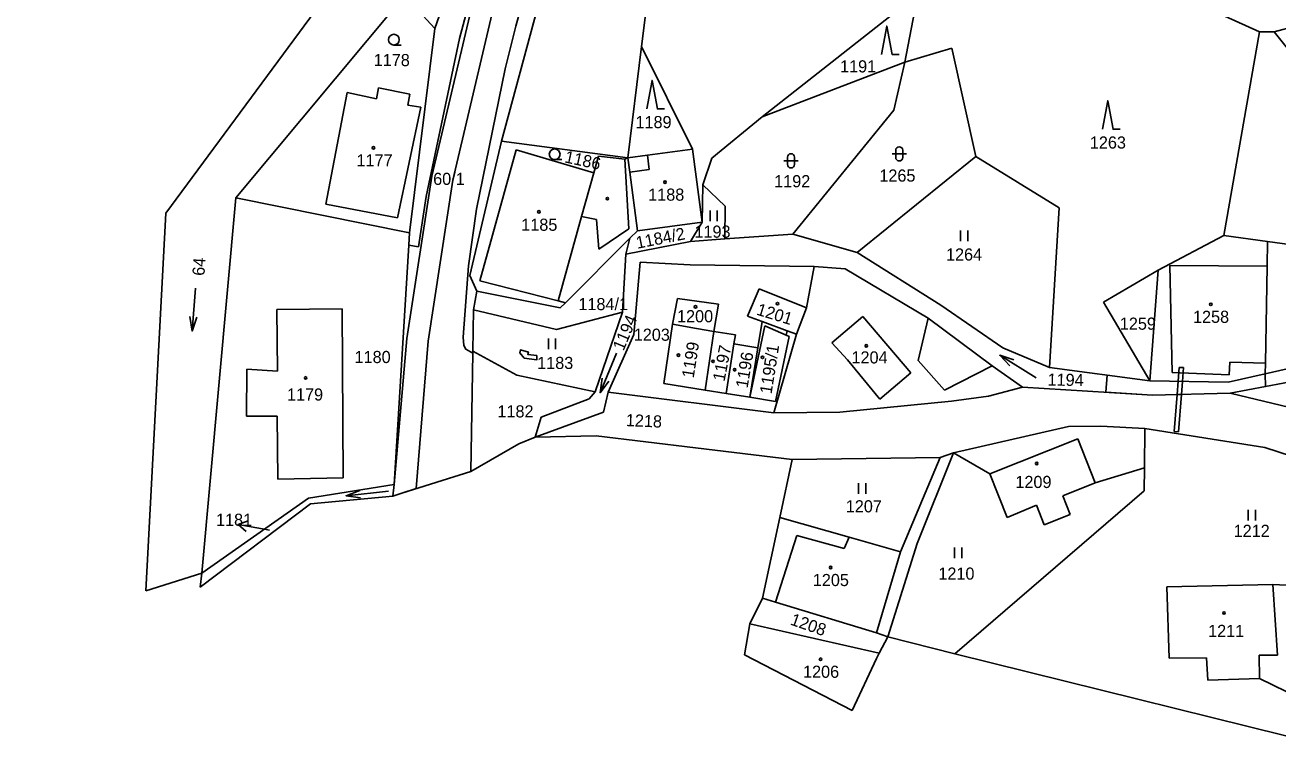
# Model space of a CAD drawing. Extents: x -670359 to -660124, y -978807 to -970072.
# Drawn here: x -670226.4 to -670050.9, y -978154.2 to -978052.1 of the extents above; entities that cross this region are included whole.
import ezdxf

# ---------------------------------------------------------------- set-up
doc = ezdxf.new("R2010")
doc.units = 0
for name, color, linetype in [('Hranice kat_území', 7, 'Continuous'), ('Hranice parcel', 7, 'Continuous'), ('Parcelní čísla', 7, 'Continuous'), ('Vnitřní kresba', 7, 'Continuous'), ('Věcná břemena k části', 7, 'Continuous'), ('Značky budov', 7, 'Continuous'), ('Značky kultur', 7, 'Continuous')]:
    doc.layers.add(name, color=color, linetype=linetype)

msp = doc.modelspace()

# ---------------------------------------------------------------- linework, layer by layer
at = {"layer": 'Hranice kat_území'}
for points in [[(-670206.64, -978078.45), (-670182.02, -978044.99)], [(-670209.48, -978131.38), (-670206.64, -978078.45)], [(-670157.22, -978110.78), (-670154.93, -978109.83)], [(-670154.93, -978109.83), (-670146.36, -978109.64)], [(-670146.36, -978109.64), (-670132.46, -978111.32)], [(-670163.94, -978114.63), (-670157.22, -978110.78)], [(-670132.46, -978111.32), (-670118.94, -978112.96)], [(-670120.66, -978121.07), (-670118.94, -978112.96)], [(-670173.62, -978117.69), (-670163.94, -978114.63)], [(-670186.41, -978119.18), (-670174.87, -978118.08)], [(-670174.87, -978118.08), (-670173.62, -978117.69)], [(-670201.87, -978130.85), (-670186.41, -978119.18)], [(-670123.06, -978132.41), (-670120.66, -978121.07)], [(-670209.48, -978131.38), (-670201.62, -978128.9)], [(-670201.62, -978128.9), (-670201.87, -978130.85)], [(-670124.85, -978136.01), (-670123.06, -978132.41)], [(-670125.58, -978140.33), (-670124.85, -978136.01)], [(-670106.72, -978140.12), (-670105.53, -978137.83)], [(-670105.53, -978137.83), (-670096.14, -978140.17)], [(-670125.58, -978140.33), (-670110.53, -978148.14)], [(-670110.53, -978148.14), (-670107.1, -978140.86)], [(-670107.1, -978140.86), (-670106.72, -978140.12)], [(-670096.14, -978140.17), (-670039.59, -978154.22)]]:
    msp.add_lwpolyline(points, dxfattribs=at)
at = {"layer": 'Hranice parcel'}
for p, q in [((-670123.73, -978097.32), (-670123.14, -978093.61)), ((-670123.14, -978093.61), (-670119.64, -978094.92)), ((-670119.64, -978094.92), (-670119.75, -978095.56)), ((-670124.83, -978104.24), (-670123.73, -978097.32)), ((-670121.25, -978104.82), (-670124.83, -978104.24)), ((-670091.23, -978114.98), (-670096.34, -978112.05)), ((-670088.81, -978121.11), (-670091.23, -978114.98)), ((-670076.46, -978116.25), (-670069.58, -978114.15)), ((-670076.46, -978116.25), (-670080.99, -978118.05)), ((-670080.99, -978118.05), (-670079.96, -978120.65)), ((-670084.69, -978119.35), (-670088.81, -978121.11)), ((-670083.6, -978122.1), (-670084.69, -978119.35)), ((-670079.96, -978120.65), (-670083.6, -978122.1))]:
    msp.add_line(p, q, dxfattribs=at)
for points in [[(-670172.63, -978082.94), (-670171.28, -978083.15), (-670170.18, -978076.11), (-670165.52, -978053.97), (-670162.38, -978042.27), (-670156.72, -978020.75), (-670154.86, -978010.1), (-670154.63, -978006.17), (-670154.76, -977993.05), (-670158.01, -977978.52), (-670176.81, -977929.42)], [(-670163.67, -978098.07), (-670164.62, -978097.52), (-670164.93, -978097), (-670165.03, -978095.83), (-670164.26, -978085.83), (-670163.16, -978077.87), (-670159.11, -978058.23), (-670157.62, -978052.26), (-670152.59, -978034.05), (-670149.21, -978019.82), (-670148.28, -978014.22), (-670147.57, -978006.49), (-670147.34, -977998.17), (-670147.68, -977989.98), (-670148.49, -977985.18)], [(-670148.99, -978028.93), (-670159.63, -978068.36)], [(-670136.86, -978029.74), (-670140.01, -978055.12)], [(-670164.52, -978039.85), (-670168.99, -978052.57)], [(-670083.53, -978039.41), (-670053.47, -978053.05)], [(-670196.85, -978076.29), (-670173.76, -978048.61)], [(-670123.1, -978064.97), (-670101.33, -978047.75)], [(-670101.33, -978047.75), (-670103.12, -978057.29)], [(-670168.99, -978052.57), (-670171.72, -978049.59)], [(-670048.28, -978052.22), (-670051.39, -978053.04)], [(-670168.99, -978052.57), (-670172.53, -978081.22)], [(-670053.47, -978053.05), (-670058.45, -978081.6)], [(-670051.39, -978053.04), (-670053.47, -978053.05)], [(-670140.01, -978055.12), (-670141.94, -978070.7)], [(-670132.87, -978069.5), (-670140.01, -978055.12)], [(-670103.12, -978057.29), (-670096.54, -978055.34)], [(-670096.54, -978055.34), (-670093.21, -978070.49)], [(-670123.1, -978064.97), (-670103.12, -978057.29)], [(-670103.12, -978057.29), (-670104.69, -978064)], [(-670177.17, -978062.41), (-670176.85, -978060.87)], [(-670176.85, -978060.87), (-670172.46, -978061.78)], [(-670184.26, -978077.21), (-670181.26, -978061.55)], [(-670181.26, -978061.55), (-670177.17, -978062.41)], [(-670172.46, -978061.78), (-670172.78, -978063.33)], [(-670170.95, -978063.58), (-670174.2, -978079.09)], [(-670172.78, -978063.33), (-670170.95, -978063.58)], [(-670104.69, -978064), (-670118.83, -978081.4)], [(-670130.19, -978070.75), (-670123.1, -978064.97)], [(-670159.63, -978068.36), (-670164.09, -978087.2)], [(-670162.66, -978087.94), (-670157.59, -978069.58)], [(-670141.94, -978070.7), (-670159.63, -978068.36)], [(-670157.59, -978069.58), (-670146.69, -978072.78)], [(-670132.87, -978069.5), (-670139.2, -978070.34)], [(-670131.53, -978079.72), (-670132.87, -978069.5)], [(-670146.69, -978072.78), (-670146.04, -978070.47)], [(-670146.04, -978070.47), (-670142.36, -978070.9)], [(-670142.36, -978070.9), (-670141.94, -978070.7)], [(-670139.2, -978070.34), (-670141.94, -978070.7)], [(-670141.94, -978070.7), (-670141.68, -978072.7)], [(-670131.42, -978074.5), (-670130.19, -978070.75)], [(-670093.21, -978070.49), (-670109.81, -978083.95)], [(-670093.21, -978070.49), (-670081.51, -978077.7)], [(-670141.68, -978072.7), (-670140.6, -978080.91)], [(-670131.53, -978079.72), (-670131.42, -978074.5)], [(-670131.42, -978074.5), (-670128.32, -978077.49)], [(-670201.62, -978128.9), (-670196.85, -978076.29)], [(-670172.53, -978081.22), (-670196.85, -978076.29)], [(-670174.2, -978079.09), (-670184.26, -978077.21)], [(-670128.32, -978077.49), (-670128.36, -978082.05)], [(-670081.51, -978077.7), (-670082.88, -978100.08)], [(-670140.6, -978080.91), (-670131.53, -978079.72)], [(-670131.53, -978079.72), (-670133.16, -978082.41)], [(-670172.53, -978081.22), (-670172.63, -978082.94)], [(-670150.69, -978090.99), (-670141.65, -978081.96)], [(-670141.65, -978081.96), (-670142.22, -978084.18)], [(-670140.6, -978080.91), (-670141.65, -978081.96)], [(-670128.36, -978082.05), (-670133.16, -978082.41)], [(-670118.83, -978081.4), (-670128.36, -978082.05)], [(-670109.81, -978083.95), (-670118.83, -978081.4)], [(-670058.45, -978081.6), (-670067.65, -978086.44)], [(-670058.45, -978081.6), (-670052.31, -978082.43)], [(-670172.63, -978082.94), (-670174.67, -978116.45)], [(-670133.16, -978082.41), (-670142.22, -978084.18)], [(-670052.31, -978082.43), (-670052.38, -978085.89)], [(-670052.31, -978082.43), (-670030.83, -978085.37)], [(-670142.22, -978084.18), (-670142.69, -978092.33)], [(-670141.11, -978095.46), (-670140.23, -978085.31)], [(-670140.23, -978085.31), (-670133.19, -978085.69)], [(-670098.1, -978091.32), (-670109.81, -978083.95)], [(-670164.09, -978087.2), (-670163.07, -978089.37)], [(-670133.19, -978085.69), (-670115.82, -978085.9)], [(-670115.82, -978085.9), (-670116.91, -978091.73)], [(-670111.51, -978086.26), (-670115.82, -978085.9)], [(-670099.87, -978093.15), (-670111.51, -978086.26)], [(-670067.65, -978086.44), (-670075.29, -978090.94)], [(-670067.65, -978086.44), (-670068.81, -978101.95)], [(-670052.38, -978085.89), (-670052.63, -978099.48)], [(-670151.68, -978090.74), (-670162.66, -978087.94)], [(-670123.53, -978089.04), (-670125.16, -978092.87)], [(-670116.91, -978091.73), (-670123.53, -978089.04)], [(-670163.07, -978089.37), (-670163.57, -978092.01)], [(-670151.4, -978091.7), (-670163.07, -978089.37)], [(-670150.69, -978090.99), (-670151.68, -978090.74)], [(-670134.99, -978090.39), (-670135.66, -978093.99)], [(-670129.26, -978091.21), (-670134.99, -978090.39)], [(-670191.1, -978091.95), (-670181.94, -978091.86)], [(-670191.01, -978100.59), (-670191.1, -978091.95)], [(-670181.94, -978091.86), (-670181.84, -978115.54)], [(-670163.57, -978092.01), (-670163.66, -978097.77)], [(-670151.91, -978094.74), (-670163.57, -978092.01)], [(-670142.69, -978092.33), (-670151.91, -978094.74)], [(-670150.69, -978090.99), (-670151.4, -978091.7)], [(-670142.69, -978092.33), (-670146.53, -978103.5)], [(-670129.87, -978095.01), (-670129.26, -978091.21)], [(-670116.91, -978091.73), (-670118.3, -978095.4)], [(-670089.42, -978097.31), (-670098.1, -978091.32)], [(-670075.29, -978090.94), (-670068.81, -978101.95)], [(-670135.66, -978093.99), (-670136.92, -978102.3)], [(-670132.32, -978094.62), (-670135.66, -978093.99)], [(-670125.16, -978092.87), (-670123.14, -978093.61)], [(-670090.88, -978099.86), (-670099.87, -978093.15)], [(-670144.69, -978103.51), (-670141.11, -978095.46)], [(-670129.87, -978095.01), (-670132.32, -978094.62)], [(-670131.12, -978103.23), (-670129.87, -978095.01)], [(-670126.88, -978095.5), (-670129.87, -978095.01)], [(-670127.09, -978096.78), (-670126.88, -978095.5)], [(-670118.3, -978095.4), (-670121.47, -978106.42)], [(-670119.32, -978095.75), (-670121.25, -978104.82)], [(-670119.75, -978095.56), (-670119.32, -978095.75)], [(-670119.64, -978094.92), (-670118.3, -978095.4)], [(-670163.66, -978097.77), (-670163.67, -978098.07)], [(-670157.48, -978101.17), (-670163.66, -978097.77)], [(-670128.16, -978103.71), (-670127.09, -978096.78)], [(-670123.73, -978097.32), (-670127.09, -978096.78)], [(-670082.88, -978100.08), (-670089.42, -978097.31)], [(-670163.67, -978098.07), (-670163.94, -978114.63)], [(-670052.63, -978099.48), (-670052.65, -978100.95)], [(-670195.38, -978106.91), (-670195.33, -978100.32)], [(-670195.33, -978100.32), (-670191.01, -978100.59)], [(-670146.53, -978103.5), (-670157.48, -978101.17)], [(-670086.67, -978102.85), (-670090.88, -978099.86)], [(-670068.81, -978101.95), (-670082.88, -978100.08)], [(-670052.65, -978100.95), (-670057.85, -978102.12)], [(-670047.51, -978099.8), (-670052.65, -978100.95)], [(-670131.12, -978103.23), (-670136.92, -978102.3)], [(-670091.4, -978104.09), (-670086.67, -978102.85)], [(-670086.67, -978102.85), (-670068.43, -978103.95)], [(-670057.85, -978102.12), (-670068.81, -978101.95)], [(-670057.54, -978103.68), (-670047.68, -978101.8)], [(-670147.34, -978104.45), (-670154.09, -978107.04)], [(-670146.53, -978103.5), (-670147.34, -978104.45)], [(-670145.36, -978106.31), (-670144.69, -978103.51)], [(-670121.47, -978106.42), (-670144.69, -978103.51)], [(-670131.12, -978103.23), (-670128.16, -978103.71)], [(-670128.16, -978103.71), (-670124.83, -978104.24)], [(-670112.22, -978106.33), (-670096.6, -978104.81)], [(-670096.6, -978104.81), (-670091.4, -978104.09)], [(-670068.43, -978103.95), (-670057.54, -978103.68)], [(-670042.2, -978107.36), (-670057.54, -978103.68)], [(-670154.93, -978109.83), (-670145.36, -978106.31)], [(-670121.47, -978106.42), (-670112.22, -978106.33)], [(-670191.06, -978106.91), (-670195.38, -978106.91)], [(-670190.97, -978115.71), (-670191.06, -978106.91)], [(-670154.09, -978107.04), (-670154.93, -978109.83)], [(-670080.23, -978108.34), (-670096.34, -978112.05)], [(-670075.69, -978108.28), (-670080.23, -978108.34)], [(-670069.51, -978108.62), (-670075.69, -978108.28)], [(-670069.51, -978108.62), (-670069.58, -978114.15)], [(-670052.72, -978111.28), (-670069.51, -978108.62)], [(-670037.63, -978116.19), (-670052.72, -978111.28)], [(-670098.19, -978112.68), (-670118.94, -978112.96)], [(-670096.34, -978112.05), (-670101.4, -978124.73)], [(-670096.34, -978112.05), (-670098.19, -978112.68)], [(-670069.58, -978114.15), (-670069.63, -978117.37)], [(-670181.84, -978115.54), (-670190.97, -978115.71)], [(-670174.67, -978116.45), (-670186.66, -978118.38)], [(-670174.87, -978118.08), (-670174.67, -978116.45)], [(-670186.66, -978118.38), (-670201.62, -978128.9)], [(-670069.63, -978117.37), (-670096.14, -978140.17)], [(-670110.92, -978123.86), (-670120.66, -978121.07)], [(-670103.73, -978125.91), (-670110.92, -978123.86)], [(-670107.1, -978137.24), (-670103.73, -978125.91)], [(-670101.4, -978124.73), (-670105.53, -978137.83)], [(-670066.44, -978130.8), (-670051.59, -978130.48)], [(-670066.11, -978140.81), (-670066.44, -978130.8)], [(-670051.59, -978130.48), (-670047.83, -978130.67)], [(-670121.24, -978132.97), (-670123.06, -978132.41)], [(-670107.1, -978137.24), (-670121.24, -978132.97)], [(-670106.72, -978140.12), (-670124.85, -978136.01)], [(-670105.53, -978137.83), (-670107.1, -978137.24)], [(-670060.87, -978140.73), (-670066.11, -978140.81)], [(-670060.7, -978143.89), (-670060.87, -978140.73)], [(-670053.45, -978143.66), (-670060.7, -978143.89)], [(-670049.7, -978145.45), (-670053.45, -978143.66)]]:
    msp.add_lwpolyline(points, dxfattribs=at)
at = {"layer": 'Parcelní čísla'}
for p, q in [((-670195.4, -978123.05), (-670196.55, -978122.09)), ((-670192.14, -978122.86), (-670192.61, -978122.78))]:
    msp.add_line(p, q, dxfattribs=at)
msp.add_lwpolyline([(-670192.61, -978122.78), (-670196.55, -978122.09), (-670195.14, -978121.57)], dxfattribs=at)
at = {"layer": 'Vnitřní kresba'}
for p, q in [((-670124.83, -978104.24), (-670122.74, -978094.22)), ((-670122.74, -978094.22), (-670119.75, -978095.56)), ((-670091.23, -978114.98), (-670078.91, -978110.08)), ((-670078.91, -978110.08), (-670076.46, -978116.25))]:
    msp.add_line(p, q, dxfattribs=at)
for points in [[(-670043.98, -978062.35), (-670051.39, -978053.04)], [(-670141.79, -978080.66), (-670142.36, -978070.9)], [(-670138.94, -978072.34), (-670139.2, -978070.34)], [(-670148.42, -978078.93), (-670146.69, -978072.78)], [(-670141.68, -978072.7), (-670138.94, -978072.34)], [(-670151.68, -978090.74), (-670148.42, -978078.93)], [(-670148.42, -978078.93), (-670146.35, -978079.35)], [(-670146.35, -978079.35), (-670145.98, -978083.51)], [(-670145.98, -978083.51), (-670141.79, -978080.66)], [(-670052.38, -978085.89), (-670066, -978085.8)], [(-670066, -978085.8), (-670065.68, -978100.78)], [(-670113.36, -978096.62), (-670109, -978092.92)], [(-670109, -978092.92), (-670102.3, -978100.81)], [(-670099.87, -978093.15), (-670101.28, -978099.11)], [(-670111.19, -978099.01), (-670113.36, -978096.62)], [(-670106.66, -978104.51), (-670111.19, -978099.01)], [(-670101.28, -978099.11), (-670097.56, -978103.26)], [(-670057.72, -978101.08), (-670057.59, -978099.32)], [(-670057.59, -978099.32), (-670052.63, -978099.48)], [(-670102.3, -978100.81), (-670106.66, -978104.51)], [(-670097.56, -978103.26), (-670090.88, -978099.86)], [(-670065.68, -978100.78), (-670057.72, -978101.08)], [(-670098.19, -978112.68), (-670103.73, -978125.91)], [(-670121.24, -978132.97), (-670118.28, -978123.6)], [(-670118.28, -978123.6), (-670111.65, -978125.45)], [(-670111.65, -978125.45), (-670110.92, -978123.86)], [(-670051.59, -978130.48), (-670050.94, -978140.36)], [(-670050.94, -978140.36), (-670053.51, -978140.38)], [(-670053.51, -978140.38), (-670053.45, -978143.66)]]:
    msp.add_lwpolyline(points, dxfattribs=at)
at = {"layer": 'Věcná břemena k části'}
for p, q in [((-670065.41, -978109.06), (-670065, -978103.86)), ((-670064.4, -978103.85), (-670064.81, -978109.1)), ((-670064.81, -978109.1), (-670065.41, -978109.06))]:
    msp.add_line(p, q, dxfattribs=at)
for points in [[(-670159.21, -978043.03), (-670166.44, -978073.84), (-670169.93, -978096.39), (-670171.6, -978117.05), (-670173.62, -978117.69), (-670174.87, -978118.08), (-670174.67, -978116.45), (-670172.91, -978096.03), (-670169.38, -978073.26), (-670162.13, -978042.33), (-670155.29, -978015.05), (-670154.43, -977993.25), (-670155.41, -977986.38), (-670176.81, -977929.42), (-670177.71, -977925.53), (-670186.89, -977901.98), (-670197.75, -977874.12), (-670224.71, -977806.51), (-670226.38, -977803.45)], [(-670156.46, -978098.77), (-670157.09, -978098.04), (-670156.98, -978097.61), (-670155.87, -978097.91), (-670155.97, -978098.25), (-670154.69, -978098.4), (-670154.71, -978099), (-670156.46, -978098.77)], [(-670052.65, -978100.95), (-670052.62, -978102.74), (-670057.54, -978103.68), (-670068.43, -978103.95), (-670074.99, -978103.55), (-670074.8, -978101.15), (-670068.81, -978101.95), (-670057.85, -978102.12), (-670052.65, -978100.95)], [(-670064.7, -978100.07), (-670064.1, -978100.09), (-670064.25, -978102.02), (-670064.85, -978102.01), (-670064.7, -978100.07)], [(-670064.85, -978102.01), (-670064.25, -978102.02), (-670064.4, -978103.85), (-670065, -978103.86), (-670064.85, -978102.01)], [(-670065, -978103.86), (-670064.4, -978103.85)]]:
    msp.add_lwpolyline(points, dxfattribs=at)
at = {"layer": 'Značky budov'}
for centre in [(-670177.58, -978069.29), (-670136.73, -978074.1), (-670154.4, -978078.26), (-670132.46, -978091.57), (-670120.98, -978091.14), (-670060.27, -978091.22), (-670108.54, -978097.04), (-670134.85, -978098.34), (-670130, -978099.2), (-670123.08, -978098.64), (-670187.08, -978101.53), (-670126.98, -978100.39), (-670084.66, -978113.53), (-670113.53, -978128.1), (-670058.42, -978134.46), (-670114.94, -978140.95)]:
    msp.add_circle(centre, 0.175, dxfattribs=at)
at = {"layer": 'Značky kultur'}
for p, q in [((-670174.71, -978054.89), (-670173.71, -978054.89)), ((-670104.42, -978069.64), (-670104.42, -978070.64)), ((-670103.42, -978069.64), (-670103.42, -978070.64)), ((-670152.19, -978070.95), (-670151.19, -978070.95)), ((-670120.08, -978071.12), (-670118.08, -978071.12)), ((-670119.58, -978070.62), (-670119.58, -978071.62)), ((-670118.58, -978070.62), (-670118.58, -978071.62)), ((-670104.92, -978070.14), (-670102.92, -978070.14)), ((-670130.41, -978078.06), (-670130.41, -978079.56)), ((-670129.41, -978079.56), (-670129.41, -978078.06)), ((-670095.33, -978080.89), (-670095.33, -978082.39)), ((-670094.33, -978082.39), (-670094.33, -978080.89)), ((-670202.49, -978088.98), (-670202.99, -978094.96)), ((-670153.06, -978096), (-670153.06, -978097.5)), ((-670152.06, -978097.5), (-670152.06, -978096)), ((-670143.51, -978098.08), (-670145.83, -978103.62)), ((-670084.75, -978101.53), (-670089.85, -978098.35)), ((-670109.61, -978116.29), (-670109.61, -978117.79)), ((-670108.61, -978117.79), (-670108.61, -978116.29)), ((-670175.46, -978117.38), (-670181.42, -978118.04)), ((-670055.03, -978120), (-670055.03, -978121.5)), ((-670054.03, -978121.5), (-670054.03, -978120)), ((-670096.16, -978125.28), (-670096.16, -978126.78)), ((-670095.16, -978126.78), (-670095.16, -978125.28))]:
    msp.add_line(p, q, dxfattribs=at)
for points in [[(-670106.41, -978056.23), (-670105.66, -978052.23), (-670104.91, -978056.23), (-670103.91, -978056.23)], [(-670139.3, -978063.84), (-670138.55, -978059.84), (-670137.8, -978063.84), (-670136.8, -978063.84)], [(-670075.47, -978066.7), (-670074.72, -978062.7), (-670073.97, -978066.7), (-670072.97, -978066.7)], [(-670202.32, -978093.01), (-670202.99, -978094.96), (-670203.32, -978092.93)], [(-670088.41, -978099.84), (-670089.85, -978098.35), (-670087.88, -978098.99)], [(-670144.6, -978101.97), (-670145.83, -978103.62), (-670145.52, -978101.58)], [(-670179.38, -978118.32), (-670181.42, -978118.04), (-670179.49, -978117.32)]]:
    msp.add_lwpolyline(points, dxfattribs=at)
for centre, radius in [((-670174.71, -978054.14), 0.75), ((-670177.58, -978069.29), 0.175), ((-670152.19, -978070.2), 0.75), ((-670136.73, -978074.1), 0.175), ((-670144.81, -978076.42), 0.175), ((-670154.4, -978078.26), 0.175), ((-670132.46, -978091.57), 0.175), ((-670120.98, -978091.14), 0.175), ((-670060.27, -978091.22), 0.175), ((-670108.54, -978097.04), 0.175), ((-670134.85, -978098.34), 0.175), ((-670130, -978099.2), 0.175), ((-670123.08, -978098.64), 0.175), ((-670187.08, -978101.53), 0.175), ((-670126.98, -978100.39), 0.175), ((-670084.66, -978113.53), 0.175), ((-670113.53, -978128.1), 0.175), ((-670058.42, -978134.46), 0.175), ((-670114.94, -978140.95), 0.175)]:
    msp.add_circle(centre, radius, dxfattribs=at)
for centre, start, end in [((-670103.92, -978069.64), 0, 180), ((-670119.08, -978070.62), 0, 180), ((-670103.92, -978070.64), 180, 0), ((-670119.08, -978071.62), 180, 0)]:
    msp.add_arc(centre, 0.5, start, end, dxfattribs=at)

# ---------------------------------------------------------------- texts
at = {"layer": 'Parcelní čísla'}
for s, height, p in [('1178', 1.7, (-670177.54, -978057.85)), ('1191', 1.7, (-670112.21, -978058.73)), ('1189', 1.7, (-670140.87, -978066.54)), ('1263', 1.7, (-670077.22, -978069.4)), ('1177', 1.7, (-670179.94, -978071.89)), ('60/1', 1.7, (-670169.21, -978074.49)), ('1192', 1.7, (-670121.44, -978074.82)), ('1265', 1.7, (-670106.71, -978074.03)), ('1188', 1.7, (-670139.09, -978076.7)), ('1185', 1.7, (-670156.87, -978080.92)), ('1193', 1.7, (-670132.61, -978081.89)), ('1264', 1.7, (-670097.37, -978085.09)), ('1184/1', 1.7, (-670148.87, -978092.04)), ('1200', 1.7, (-670135.05, -978093.74)), ('1258', 1.7, (-670062.77, -978093.82)), ('1259', 1.7, (-670073.02, -978094.78)), ('1203', 1.7, (-670141.11, -978096.33)), ('1180', 1.7, (-670180.22, -978099.45)), ('1204', 1.7, (-670110.61, -978099.51)), ('1183', 1.7, (-670154.64, -978100.28)), ('1179', 1.7, (-670189.69, -978104.71)), ('1182', 1.7, (-670160.21, -978107.07)), ('1209', 1.7, (-670087.65, -978116.96)), ('1207', 1.7, (-670111.41, -978120.37)), ('1181', 1.7, (-670199.63, -978122.26)), ('1212', 1.7, (-670057.08, -978123.81)), ('1181', 0.1, (-670192.14, -978122.86)), ('1205', 1.7, (-670116.03, -978130.7)), ('1210', 1.7, (-670098.44, -978129.8)), ('1211', 1.7, (-670060.65, -978137.83)), ('1206', 1.7, (-670117.4, -978143.55))]:
    msp.add_text(s, height=height, dxfattribs=at).set_placement(p)
for s, rotation, p in [('1186', 347.7709, (-670150.89, -978071.32)), ('1184/2', 11.2317, (-670140.62, -978083.45)), ('64', 85.9219, (-670201.26, -978087.27)), ('1201', 342.9698, (-670124.02, -978092.65)), ('1194', 67.1139, (-670142.55, -978097.84)), ('1199', 80.9724, (-670132.72, -978101.62)), ('1197', 78.9485, (-670128.4, -978102.1)), ('1195/1', 81, (-670121.81, -978103.86)), ('1196', 80.4171, (-670125.17, -978103.04)), ('1194', 359.1589, (-670083.15, -978102.61)), ('1218', 357.5067, (-670142.25, -978108.28)), ('1208', 340.8476, (-670119.3, -978136.07))]:
    msp.add_text(s, height=1.7, rotation=rotation, dxfattribs=at).set_placement(p)

doc.saveas('drawing.dxf')
